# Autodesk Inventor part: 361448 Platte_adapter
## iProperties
Created: 2007-02
Part Number: 361448 Platte_adapter
Material: 1.0037         St 37-2
Document SubType Name: Modellieren
Designer: Ing.- und Konstrukti
Density: 7.87 g/cm^3
Mass: 1157.7 g
Surface Area: 422.861 cm^2
Volume: 147.103 cm^3
Author: Ing.- und Konstrukti
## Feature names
1. Extrusion1
2. Bohrung1 [Hole]
3. Rechteckige Anordnung1 [Rectangular Pattern]
4. Bohrung2 [Hole]
5. Spiegeln1 [Mirror]
